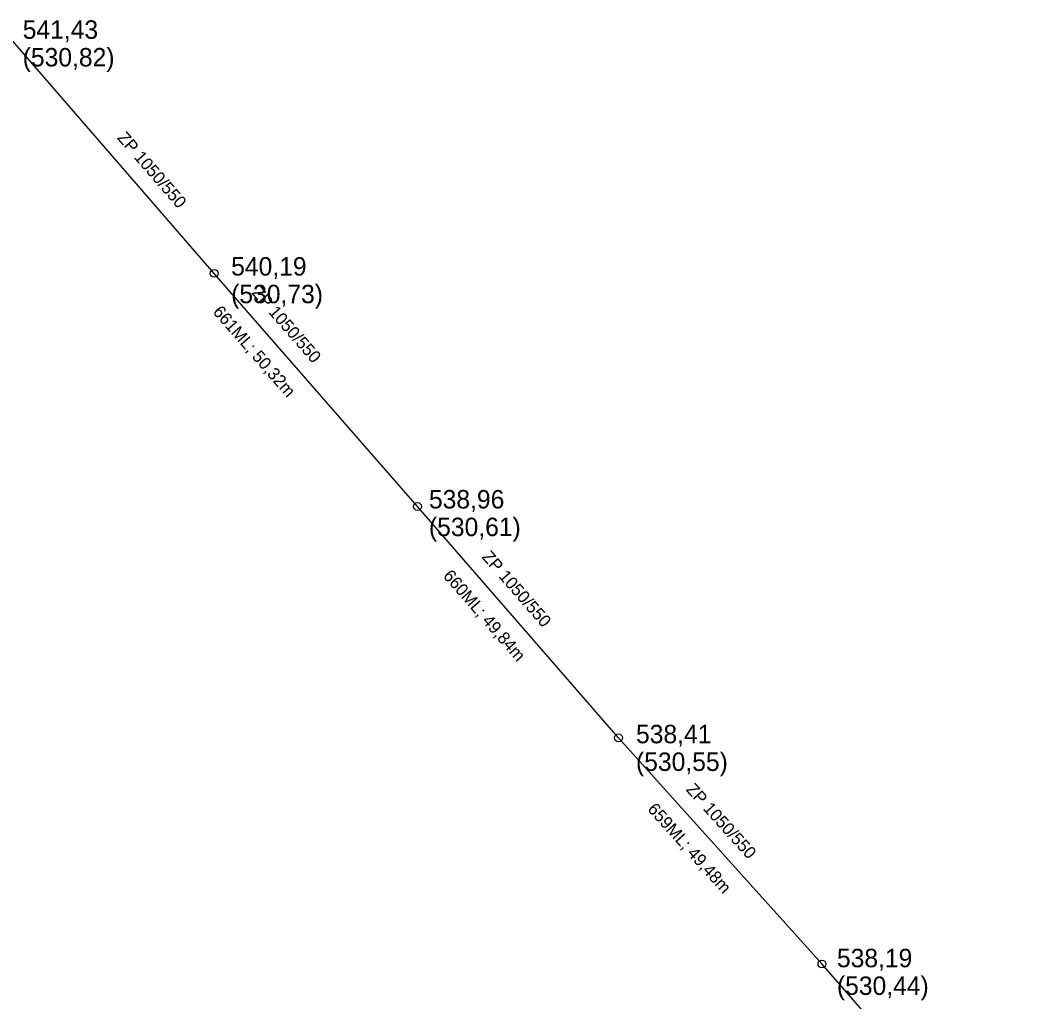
# Model space of a CAD drawing. Extents: x -867696 to -865033, y -1042522 to -1039817.
# Drawn here: x -866771.3 to -866608, y -1041184.7 to -1041025 of the extents above; entities that cross this region are included whole.
import ezdxf

# ---------------------------------------------------------------- set-up
doc = ezdxf.new("R2010")
doc.units = 0
for name, color, linetype in [('KN - jednotna', 7, 'Continuous'), ('KN - popis material', 7, 'Continuous'), ('KN - popis ostatni', 7, 'Continuous'), ('KN - popis usek delka', 7, 'Continuous'), ('KN - sachta komora', 7, 'Continuous'), ('Level 1', 7, 'Continuous')]:
    doc.layers.add(name, color=color, linetype=linetype)

# ---------------------------------------------------------------- blocks, each defined once
blk = doc.blocks.new('100.M')
at = {"layer": 'Level 1'}
blk.add_circle((0, 0), 1.27, dxfattribs=at)

msp = doc.modelspace()

# ---------------------------------------------------------------- linework, layer by layer
at = {"layer": 'KN - jednotna'}
for points in [[(-866739.728, -1041066.158), (-866772.797, -1041028.018)], [(-866706.647, -1041104.079), (-866739.728, -1041066.158)], [(-866673.947, -1041141.698), (-866706.647, -1041104.079)], [(-866640.847, -1041178.479), (-866673.947, -1041141.698)], [(-866607.979, -1041216.198), (-866640.847, -1041178.479)]]:
    msp.add_lwpolyline(points, dxfattribs=at)

# ---------------------------------------------------------------- block references
at = {"layer": 'KN - sachta komora', "xscale": 0.5000000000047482, "yscale": 0.5000000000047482, "rotation": 132.0000013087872}
for p in [(-866739.728, -1041066.158), (-866706.647, -1041104.079), (-866673.947, -1041141.698), (-866640.847, -1041178.479)]:
    msp.add_blockref('100.M', p, dxfattribs=at)

# ---------------------------------------------------------------- texts
at = {"layer": 'KN - popis material'}
for rotation, p in [(310.93, (-866755.608, -1041044.18)), (311.1, (-866733.737, -1041069.376)), (311, (-866696.285, -1041112.341)), (311.98, (-866663.078, -1041150.186))]:
    msp.add_text('ZP 1050/550', height=1.99999, rotation=rotation, dxfattribs=at).set_placement(p)
at = {"layer": 'KN - popis ostatni'}
for s, p in [('541,43 ', (-866770.887, -1041028.008)), ('(530,82)', (-866770.887, -1041032.508)), ('540,19 ', (-866736.968, -1041066.518)), ('(530,73)', (-866736.968, -1041071.018)), ('538,96 ', (-866704.787, -1041104.399)), ('(530,61)', (-866704.787, -1041108.899)), ('538,41 ', (-866671.097, -1041142.588)), ('(530,55)', (-866671.097, -1041147.088)), ('538,19 ', (-866638.407, -1041179.019)), ('(530,44)', (-866638.407, -1041183.519))]:
    msp.add_text(s, height=3, dxfattribs=at).set_placement(p)
at = {"layer": 'KN - popis usek delka'}
for s, rotation, p in [('661ML; 50,32m', 311.1, (-866740.044, -1041072.489)), ('660ML; 49,84m', 311, (-866702.598, -1041115.443)), ('659ML; 49,48m', 311.98, (-866669.338, -1041153.396))]:
    msp.add_text(s, height=1.99999, rotation=rotation, dxfattribs=at).set_placement(p)

doc.saveas('drawing.dxf')
